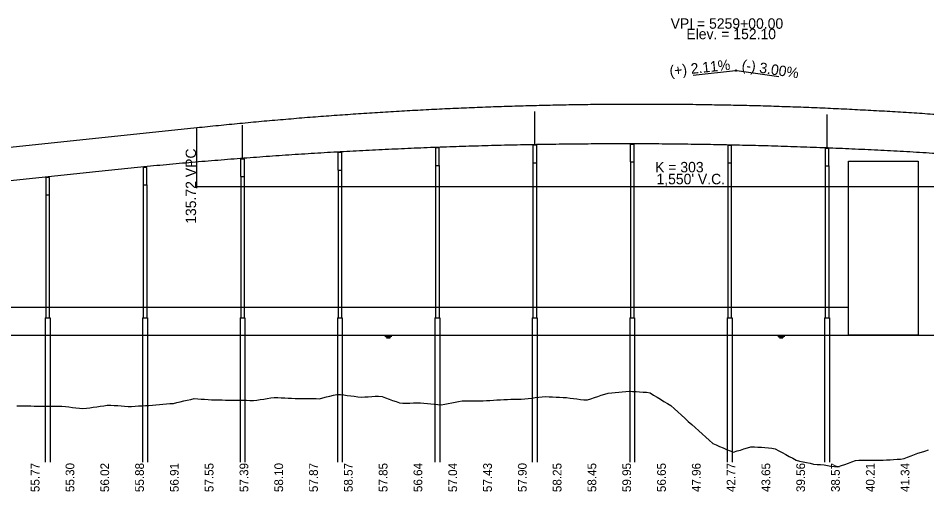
# Model space of a CAD drawing. Extents: x 2121671 to 2169879, y 557274 to 599957.
# Drawn here: x 2154437 to 2155742, y 595763 to 596443 of the extents above; entities that cross this region are included whole.
import ezdxf

# ---------------------------------------------------------------- set-up
doc = ezdxf.new("R2010")
doc.units = 0
for name, color, linetype in [('BR_CONCRETE', 7, 'Continuous'), ('BR_DETAILS', 7, 'Continuous'), ('BR_PRESTRESSED BEAM', 7, 'Continuous'), ('RD_DDB_GradeTX', 7, 'Continuous'), ('RD_DDB_Profile_Elev', 7, 'Continuous'), ('RD_DDB_Profile_EX', 7, 'Continuous'), ('RD_DDB_Profile_Lbl', 7, 'Continuous'), ('RD_DDB_Profile_PR', 7, 'Continuous'), ('RD_DDB_StripGrade', 7, 'Continuous'), ('RD_DDB_VCLbl', 7, 'Continuous')]:
    doc.layers.add(name, color=color, linetype=linetype)

msp = doc.modelspace()

# ---------------------------------------------------------------- linework, layer by layer
at = {"layer": 'BR_CONCRETE'}
for p, q in [((2155176.3, 596235.7), (2155176.3, 596013.1)), ((2155176.3, 596235.7), (2155176.3, 596013.1)), ((2155181.3, 596235.7), (2155181.3, 596013.1)), ((2155181.3, 596235.7), (2155181.3, 596013.1)), ((2155316.3, 596236.9), (2155316.3, 596013.1)), ((2155316.3, 596236.9), (2155316.3, 596013.1)), ((2155321.3, 596236.9), (2155321.3, 596013.1)), ((2155321.3, 596236.9), (2155321.3, 596013.1)), ((2155456.3, 596235.3), (2155456.3, 596013.1)), ((2155456.3, 596235.3), (2155456.3, 596013.1)), ((2155461.3, 596235.3), (2155461.3, 596013.1)), ((2155461.3, 596235.3), (2155461.3, 596013.1)), ((2154896.3, 596225.1), (2154896.3, 596013.1)), ((2154896.3, 596225.1), (2154896.3, 596013.1)), ((2154901.3, 596225.1), (2154901.3, 596013.1)), ((2154901.3, 596225.1), (2154901.3, 596013.1)), ((2155036.3, 596231.8), (2155036.3, 596013.1)), ((2155036.3, 596231.8), (2155036.3, 596013.1)), ((2155041.3, 596231.8), (2155041.3, 596013.1)), ((2155041.3, 596231.8), (2155041.3, 596013.1)), ((2155596.3, 596231), (2155596.3, 596013.1)), ((2155596.3, 596231), (2155596.3, 596013.1)), ((2155601.3, 596231), (2155601.3, 596013.1)), ((2155601.3, 596231), (2155601.3, 596013.1)), ((2154756.3, 596215.8), (2154756.3, 596013.1)), ((2154756.3, 596215.8), (2154756.3, 596013.1)), ((2154761.3, 596215.8), (2154761.3, 596013.1)), ((2154761.3, 596215.8), (2154761.3, 596013.1)), ((2154616.3, 596203.8), (2154616.3, 596013.1)), ((2154616.3, 596203.8), (2154616.3, 596013.1)), ((2154621.3, 596203.8), (2154621.3, 596013.1)), ((2154621.3, 596203.8), (2154621.3, 596013.1)), ((2154476.3, 596189.4), (2154476.3, 596013.1)), ((2154476.3, 596189.4), (2154476.3, 596013.1)), ((2154481.3, 596189.4), (2154481.3, 596013.1)), ((2154481.3, 596189.4), (2154481.3, 596013.1)), ((2154475.3, 596013.1), (2154475.3, 595805.8)), ((2154475.3, 596013.1), (2154475.3, 595805.8)), ((2154482.3, 596013.1), (2154482.3, 595805.8)), ((2154482.3, 596013.1), (2154482.3, 595805.8)), ((2154615.3, 596013.1), (2154615.3, 595805.8)), ((2154615.3, 596013.1), (2154615.3, 595805.8)), ((2154622.3, 596013.1), (2154622.3, 595805.8)), ((2154622.3, 596013.1), (2154622.3, 595805.8)), ((2154755.3, 596013.1), (2154755.3, 595805.8)), ((2154755.3, 596013.1), (2154755.3, 595805.8)), ((2154762.3, 596013.1), (2154762.3, 595805.8)), ((2154762.3, 596013.1), (2154762.3, 595805.8)), ((2154895.3, 596013.1), (2154895.3, 595805.8)), ((2154895.3, 596013.1), (2154895.3, 595805.8)), ((2154902.3, 596013.1), (2154902.3, 595805.8)), ((2154902.3, 596013.1), (2154902.3, 595805.8)), ((2155035.3, 596013.1), (2155035.3, 595805.8)), ((2155035.3, 596013.1), (2155035.3, 595805.8)), ((2155042.3, 596013.1), (2155042.3, 595805.8)), ((2155042.3, 596013.1), (2155042.3, 595805.8)), ((2155175.3, 596013.1), (2155175.3, 595805.8)), ((2155175.3, 596013.1), (2155175.3, 595805.8)), ((2155182.3, 596013.1), (2155182.3, 595805.8)), ((2155182.3, 596013.1), (2155182.3, 595805.8)), ((2155315.3, 596013.1), (2155315.3, 595805.8)), ((2155315.3, 596013.1), (2155315.3, 595805.8)), ((2155322.3, 596013.1), (2155322.3, 595805.8)), ((2155322.3, 596013.1), (2155322.3, 595805.8)), ((2155455.3, 596013.1), (2155455.3, 595805.8)), ((2155455.3, 596013.1), (2155455.3, 595805.8)), ((2155462.3, 596013.1), (2155462.3, 595805.8)), ((2155462.3, 596013.1), (2155462.3, 595805.8)), ((2155595.3, 596013.1), (2155595.3, 595805.8)), ((2155595.3, 596013.1), (2155595.3, 595805.8)), ((2155602.3, 596013.1), (2155602.3, 595805.8)), ((2155602.3, 596013.1), (2155602.3, 595805.8))]:
    msp.add_line(p, q, dxfattribs=at)
for points in [[(2155176.1, 596235.7), (2155181.6, 596235.7), (2155181.6, 596260.7), (2155176.1, 596260.7)], [(2155176.1, 596235.7), (2155181.6, 596235.7), (2155181.6, 596260.7), (2155176.1, 596260.7)], [(2155316.1, 596236.9), (2155321.6, 596236.9), (2155321.6, 596261.9), (2155316.1, 596261.9)], [(2155316.1, 596236.9), (2155321.6, 596236.9), (2155321.6, 596261.9), (2155316.1, 596261.9)], [(2154896.1, 596225.1), (2154901.6, 596225.1), (2154901.6, 596250.1), (2154896.1, 596250.1)], [(2154896.1, 596225.1), (2154901.6, 596225.1), (2154901.6, 596250.1), (2154896.1, 596250.1)], [(2155036.1, 596231.8), (2155041.6, 596231.8), (2155041.6, 596256.8), (2155036.1, 596256.8)], [(2155036.1, 596231.8), (2155041.6, 596231.8), (2155041.6, 596256.8), (2155036.1, 596256.8)], [(2155456.1, 596235.3), (2155461.6, 596235.3), (2155461.6, 596260.3), (2155456.1, 596260.3)], [(2155456.1, 596235.3), (2155461.6, 596235.3), (2155461.6, 596260.3), (2155456.1, 596260.3)], [(2155596.1, 596231), (2155601.6, 596231), (2155601.6, 596256), (2155596.1, 596256)], [(2155596.1, 596231), (2155601.6, 596231), (2155601.6, 596256), (2155596.1, 596256)], [(2154756.1, 596215.8), (2154761.6, 596215.8), (2154761.6, 596240.8), (2154756.1, 596240.8)], [(2154756.1, 596215.8), (2154761.6, 596215.8), (2154761.6, 596240.8), (2154756.1, 596240.8)], [(2154616.1, 596203.8), (2154621.6, 596203.8), (2154621.6, 596228.8), (2154616.1, 596228.8)], [(2154616.1, 596203.8), (2154621.6, 596203.8), (2154621.6, 596228.8), (2154616.1, 596228.8)], [(2154476.1, 596189.4), (2154481.6, 596189.4), (2154481.6, 596214.4), (2154476.1, 596214.4)], [(2154476.1, 596189.4), (2154481.6, 596189.4), (2154481.6, 596214.4), (2154476.1, 596214.4)]]:
    msp.add_lwpolyline(points, close=True, dxfattribs=at)
at = {"layer": 'BR_DETAILS'}
for points in [[(2155177.3, 596261.9), (2155178.3, 596261.9), (2155178.3, 596260.7), (2155177.3, 596260.7)], [(2155177.3, 596261.9), (2155178.3, 596261.9), (2155178.3, 596260.7), (2155177.3, 596260.7)], [(2155179.3, 596261.9), (2155180.3, 596261.9), (2155180.3, 596260.7), (2155179.3, 596260.7)], [(2155179.3, 596261.9), (2155180.3, 596261.9), (2155180.3, 596260.7), (2155179.3, 596260.7)], [(2155317.3, 596263.1), (2155318.3, 596263.1), (2155318.3, 596261.9), (2155317.3, 596261.9)], [(2155317.3, 596263.1), (2155318.3, 596263.1), (2155318.3, 596261.9), (2155317.3, 596261.9)], [(2155319.3, 596263.1), (2155320.3, 596263.1), (2155320.3, 596261.9), (2155319.3, 596261.9)], [(2155319.3, 596263.1), (2155320.3, 596263.1), (2155320.3, 596261.9), (2155319.3, 596261.9)], [(2155457.3, 596261.5), (2155458.3, 596261.5), (2155458.3, 596260.3), (2155457.3, 596260.3)], [(2155457.3, 596261.5), (2155458.3, 596261.5), (2155458.3, 596260.3), (2155457.3, 596260.3)], [(2155459.3, 596261.5), (2155460.3, 596261.5), (2155460.3, 596260.3), (2155459.3, 596260.3)], [(2155459.3, 596261.5), (2155460.3, 596261.5), (2155460.3, 596260.3), (2155459.3, 596260.3)], [(2154897.3, 596251.4), (2154898.3, 596251.4), (2154898.3, 596250.1), (2154897.3, 596250.1)], [(2154897.3, 596251.4), (2154898.3, 596251.4), (2154898.3, 596250.1), (2154897.3, 596250.1)], [(2154899.3, 596251.4), (2154900.3, 596251.4), (2154900.3, 596250.1), (2154899.3, 596250.1)], [(2154899.3, 596251.4), (2154900.3, 596251.4), (2154900.3, 596250.1), (2154899.3, 596250.1)], [(2155037.3, 596258), (2155038.3, 596258), (2155038.3, 596256.8), (2155037.3, 596256.8)], [(2155037.3, 596258), (2155038.3, 596258), (2155038.3, 596256.8), (2155037.3, 596256.8)], [(2155039.3, 596258), (2155040.3, 596258), (2155040.3, 596256.8), (2155039.3, 596256.8)], [(2155039.3, 596258), (2155040.3, 596258), (2155040.3, 596256.8), (2155039.3, 596256.8)], [(2155597.3, 596257.3), (2155598.3, 596257.3), (2155598.3, 596256), (2155597.3, 596256)], [(2155597.3, 596257.3), (2155598.3, 596257.3), (2155598.3, 596256), (2155597.3, 596256)], [(2155599.3, 596257.3), (2155600.3, 596257.3), (2155600.3, 596256), (2155599.3, 596256)], [(2155599.3, 596257.3), (2155600.3, 596257.3), (2155600.3, 596256), (2155599.3, 596256)], [(2154757.3, 596242.1), (2154758.3, 596242.1), (2154758.3, 596240.8), (2154757.3, 596240.8)], [(2154757.3, 596242.1), (2154758.3, 596242.1), (2154758.3, 596240.8), (2154757.3, 596240.8)], [(2154759.3, 596242.1), (2154760.3, 596242.1), (2154760.3, 596240.8), (2154759.3, 596240.8)], [(2154759.3, 596242.1), (2154760.3, 596242.1), (2154760.3, 596240.8), (2154759.3, 596240.8)], [(2154617.3, 596230), (2154618.3, 596230), (2154618.3, 596228.8), (2154617.3, 596228.8)], [(2154617.3, 596230), (2154618.3, 596230), (2154618.3, 596228.8), (2154617.3, 596228.8)], [(2154619.3, 596230), (2154620.3, 596230), (2154620.3, 596228.8), (2154619.3, 596228.8)], [(2154619.3, 596230), (2154620.3, 596230), (2154620.3, 596228.8), (2154619.3, 596228.8)], [(2154477.3, 596215.6), (2154478.3, 596215.6), (2154478.3, 596214.4), (2154477.3, 596214.4)], [(2154477.3, 596215.6), (2154478.3, 596215.6), (2154478.3, 596214.4), (2154477.3, 596214.4)], [(2154479.3, 596215.6), (2154480.3, 596215.6), (2154480.3, 596214.4), (2154479.3, 596214.4)], [(2154479.3, 596215.6), (2154480.3, 596215.6), (2154480.3, 596214.4), (2154479.3, 596214.4)]]:
    msp.add_lwpolyline(points, close=True, dxfattribs=at)
at = {"layer": 'BR_PRESTRESSED BEAM'}
for p, q in [((2155178.8, 596261.9), (2155178.8, 596309.4)), ((2155178.8, 596261.9), (2155178.8, 596309.4)), ((2155598.8, 596257.3), (2155598.8, 596304.8)), ((2155598.8, 596257.3), (2155598.8, 596304.8)), ((2154758.8, 596242.2), (2154758.8, 596289.7)), ((2154758.8, 596242.2), (2154758.8, 596289.7)), ((2154250.2, 596191.8), (2154543.2, 596222.7)), ((2154250.2, 596191.8), (2154543.2, 596222.7)), ((2154475.3, 596013.1), (2154482.3, 596013.1)), ((2154475.3, 596013.1), (2154482.3, 596013.1)), ((2154615.3, 596013.1), (2154622.3, 596013.1)), ((2154615.3, 596013.1), (2154622.3, 596013.1)), ((2154755.3, 596013.1), (2154762.3, 596013.1)), ((2154755.3, 596013.1), (2154762.3, 596013.1)), ((2154895.3, 596013.1), (2154902.3, 596013.1)), ((2154895.3, 596013.1), (2154902.3, 596013.1)), ((2155035.3, 596013.1), (2155042.3, 596013.1)), ((2155035.3, 596013.1), (2155042.3, 596013.1)), ((2155175.3, 596013.1), (2155182.3, 596013.1)), ((2155175.3, 596013.1), (2155182.3, 596013.1)), ((2155315.3, 596013.1), (2155322.3, 596013.1)), ((2155315.3, 596013.1), (2155322.3, 596013.1)), ((2155455.3, 596013.1), (2155462.3, 596013.1)), ((2155455.3, 596013.1), (2155462.3, 596013.1)), ((2155595.3, 596013.1), (2155602.3, 596013.1)), ((2155595.3, 596013.1), (2155602.3, 596013.1))]:
    msp.add_line(p, q, dxfattribs=at)
msp.add_spline([(2154543.2, 596222.7), (2154580.2, 596226.6), (2154617.2, 596230.2), (2154654.2, 596233.6), (2154691.2, 596236.9), (2154728.2, 596239.9), (2154765.2, 596242.8), (2154802.2, 596245.5), (2154839.2, 596248), (2154876.2, 596250.3), (2154913.2, 596252.4), (2154950.2, 596254.3), (2154987.2, 596256), (2155024.2, 596257.6), (2155061.2, 596258.9), (2155098.2, 596260.1), (2155135.2, 596261.1), (2155172.2, 596261.9), (2155209.2, 596262.5), (2155246.2, 596262.9), (2155283.2, 596263.1), (2155320.2, 596263.1), (2155357.2, 596263), (2155394.2, 596262.6), (2155431.2, 596262.1), (2155468.2, 596261.3), (2155505.2, 596260.4), (2155542.2, 596259.3), (2155579.2, 596258), (2155616.2, 596256.5), (2155653.2, 596254.9), (2155690.2, 596253), (2155727.2, 596251), (2155764.2, 596248.7), (2155801.2, 596246.3), (2155838.2, 596243.7), (2155875.2, 596240.9), (2155912.2, 596237.9), (2155949.2, 596234.7), (2155986.2, 596231.3), (2156023.2, 596227.7), (2156060.2, 596224), (2156097.2, 596220.1), (2156134.2, 596215.9), (2156171.2, 596211.6), (2156208.2, 596207.1), (2156245.2, 596202.4), (2156282.2, 596197.5), (2156319.2, 596192.4), (2156356.2, 596187.2), (2156393.2, 596181.7)], degree=3, dxfattribs=at)
msp.add_spline([(2154543.2, 596222.7), (2154580.2, 596226.6), (2154617.2, 596230.2), (2154654.2, 596233.6), (2154691.2, 596236.9), (2154728.2, 596239.9), (2154765.2, 596242.8), (2154802.2, 596245.5), (2154839.2, 596248), (2154876.2, 596250.3), (2154913.2, 596252.4), (2154950.2, 596254.3), (2154987.2, 596256), (2155024.2, 596257.6), (2155061.2, 596258.9), (2155098.2, 596260.1), (2155135.2, 596261.1), (2155172.2, 596261.9), (2155209.2, 596262.5), (2155246.2, 596262.9), (2155283.2, 596263.1), (2155320.2, 596263.1), (2155357.2, 596263), (2155394.2, 596262.6), (2155431.2, 596262.1), (2155468.2, 596261.3), (2155505.2, 596260.4), (2155542.2, 596259.3), (2155579.2, 596258), (2155616.2, 596256.5), (2155653.2, 596254.9), (2155690.2, 596253), (2155727.2, 596251), (2155764.2, 596248.7), (2155801.2, 596246.3), (2155838.2, 596243.7), (2155875.2, 596240.9), (2155912.2, 596237.9), (2155949.2, 596234.7), (2155986.2, 596231.3), (2156023.2, 596227.7), (2156060.2, 596224), (2156097.2, 596220.1), (2156134.2, 596215.9), (2156171.2, 596211.6), (2156208.2, 596207.1), (2156245.2, 596202.4), (2156282.2, 596197.5), (2156319.2, 596192.4), (2156356.2, 596187.2), (2156393.2, 596181.7)], degree=3, dxfattribs=at)
at = {"layer": 'RD_DDB_GradeTX'}
for p, q in [((2155406.6, 596361.4), (2155467.3, 596367.9)), ((2155529.6, 596358.8), (2155469.2, 596367.8))]:
    msp.add_line(p, q, dxfattribs=at)
msp.add_circle((2155468.2, 596368), 1, dxfattribs=at)
at = {"layer": 'RD_DDB_Profile_Elev'}
for p, q in [((2151940.7, 596028.1), (2155629.7, 596028.1)), ((2151972, 595988.1), (2156334.9, 595988.1)), ((2154963.4, 595986.8), (2154973.4, 595986.8)), ((2155528, 595986.8), (2155538, 595986.8)), ((2154964.7, 595985.6), (2154972.2, 595985.6)), ((2154965.9, 595984.3), (2154970.9, 595984.3)), ((2155529.3, 595985.6), (2155536.8, 595985.6)), ((2155530.5, 595984.3), (2155535.5, 595984.3))]:
    msp.add_line(p, q, dxfattribs=at)
msp.add_lwpolyline([(2155629.7, 596238.1), (2155729.7, 596238.1), (2155729.7, 595988.1), (2155629.7, 595988.1)], close=True, dxfattribs=at)
at = {"layer": 'RD_DDB_Profile_EX'}
for points in [[(2154434.5, 595886.7), (2154439.5, 595886.6), (2154444.5, 595886.6), (2154449.5, 595886.5), (2154454.5, 595886.4), (2154459.5, 595886.3), (2154464.5, 595886.3), (2154469.5, 595886.3), (2154474.5, 595886.3), (2154479.5, 595886.3), (2154484.5, 595886.3), (2154489.5, 595886.3), (2154494.5, 595886.3), (2154499.5, 595885.9), (2154504.5, 595885.4), (2154509.5, 595884.9), (2154514.5, 595884.3), (2154519.5, 595883.8), (2154524.5, 595883.3), (2154529.5, 595882.8), (2154534.5, 595883.1), (2154539.5, 595883.8), (2154544.5, 595884.5), (2154549.5, 595885.3), (2154554.5, 595886), (2154559.5, 595886.7), (2154564.5, 595887.4), (2154569.5, 595887.6), (2154574.5, 595887.2), (2154579.5, 595886.9), (2154584.5, 595886.5), (2154589.5, 595886.1), (2154594.5, 595885.7), (2154599.5, 595885.8), (2154604.5, 595886.1), (2154609.5, 595886.4), (2154614.5, 595886.7), (2154619.5, 595887), (2154624.5, 595887.2), (2154629.5, 595887.5), (2154634.5, 595887.9), (2154639.5, 595888.3), (2154644.5, 595888.8), (2154649.5, 595889.2), (2154654.5, 595889.7), (2154659.5, 595890.1), (2154664.5, 595891.2), (2154669.5, 595892.3), (2154674.5, 595893.5), (2154679.5, 595894.7), (2154684.5, 595895.8), (2154689.5, 595896.9), (2154694.5, 595896.6)], [(2154694.5, 595896.6), (2154699.5, 595896.3), (2154704.5, 595896), (2154709.5, 595895.7), (2154714.5, 595895.4), (2154719.5, 595895.2), (2154724.5, 595895.1), (2154729.5, 595895), (2154734.5, 595894.9), (2154739.5, 595894.8), (2154744.5, 595894.7), (2154749.5, 595894.8), (2154754.5, 595894.7), (2154759.5, 595894.6), (2154764.5, 595894.5), (2154769.5, 595894.4), (2154774.5, 595894.3), (2154779.5, 595894.7), (2154784.5, 595895.5), (2154789.5, 595896.3), (2154794.5, 595897.1), (2154799.5, 595897.9), (2154804.5, 595898.6), (2154809.5, 595898.4), (2154814.5, 595898.1), (2154819.5, 595897.9), (2154824.5, 595897.7), (2154829.5, 595897.4), (2154834.5, 595897.2), (2154839.5, 595897.2), (2154844.5, 595897.1), (2154849.5, 595897), (2154854.5, 595897), (2154859.5, 595896.9), (2154864.5, 595896.9), (2154869.5, 595896.8), (2154874.5, 595898), (2154879.5, 595899.3), (2154884.5, 595900.5), (2154889.5, 595901.7), (2154894.5, 595902.9), (2154899.5, 595902.9), (2154904.5, 595902.2), (2154909.5, 595901.5), (2154914.5, 595900.8), (2154919.5, 595900.2), (2154924.5, 595899.5), (2154929.5, 595899), (2154934.5, 595899.3), (2154939.5, 595899.6), (2154944.5, 595899.9), (2154949.5, 595900.2), (2154954.5, 595900.5), (2154959.5, 595900), (2154964.5, 595898.1), (2154969.5, 595896.3), (2154974.5, 595894.4), (2154979.5, 595892.6), (2154984.5, 595890.7), (2154989.5, 595890.4), (2154994.5, 595890.5), (2154999.5, 595890.6), (2155004.5, 595890.7), (2155009.5, 595890.8), (2155014.5, 595890.8), (2155019.5, 595890.6), (2155024.5, 595890.1), (2155029.5, 595889.6), (2155034.5, 595889), (2155039.5, 595888.5), (2155044.5, 595888.1), (2155049.5, 595889.1), (2155054.5, 595890), (2155059.5, 595891), (2155064.5, 595892), (2155069.5, 595892.9), (2155074.5, 595893.9), (2155079.5, 595893.9), (2155084.5, 595893.8), (2155089.5, 595893.8), (2155094.5, 595893.7), (2155099.5, 595893.7), (2155104.5, 595893.7), (2155109.5, 595894), (2155114.5, 595894.4), (2155119.5, 595894.7), (2155124.5, 595895.1), (2155129.5, 595895.4), (2155134.5, 595895.7), (2155139.5, 595895.8), (2155144.5, 595895.9), (2155149.5, 595896), (2155154.5, 595896.1), (2155159.5, 595896.2), (2155164.5, 595896.5), (2155169.5, 595897.1), (2155174.5, 595897.7), (2155179.5, 595898.3), (2155184.5, 595898.9), (2155189.5, 595899.5), (2155194.5, 595899.8)], [(2155194.5, 595899.8), (2155199.5, 595899.5), (2155204.5, 595899.3), (2155209.5, 595899.1), (2155214.5, 595898.9), (2155219.5, 595898.7), (2155224.5, 595898.4), (2155229.5, 595897.7), (2155234.5, 595897.1), (2155239.5, 595896.4), (2155244.5, 595895.7), (2155249.5, 595895), (2155254.5, 595895.1), (2155259.5, 595896.8), (2155264.5, 595898.5), (2155269.5, 595900.1), (2155274.5, 595901.8), (2155279.5, 595903.4), (2155284.5, 595904.7), (2155289.5, 595905.2), (2155294.5, 595905.7), (2155299.5, 595906.2), (2155304.5, 595906.7), (2155309.5, 595907.2), (2155314.5, 595907.4), (2155319.5, 595907.1), (2155324.5, 595906.9), (2155329.5, 595906.6), (2155334.5, 595906.4), (2155339.5, 595906.1), (2155344.5, 595905), (2155349.5, 595902), (2155354.5, 595899), (2155359.5, 595896), (2155364.5, 595893), (2155369.5, 595890), (2155374.5, 595887), (2155379.5, 595882.4), (2155384.5, 595877.8), (2155389.5, 595873.2), (2155394.5, 595868.6), (2155399.5, 595864), (2155404.5, 595859.6), (2155409.5, 595855.2), (2155414.5, 595850.7), (2155419.5, 595846.2), (2155424.5, 595841.7), (2155429.5, 595837.2), (2155434.5, 595832.6), (2155439.5, 595830.5), (2155444.5, 595828.3), (2155449.5, 595826.2), (2155454.5, 595824), (2155459.5, 595821.8), (2155464.5, 595820.2), (2155469.5, 595821.7), (2155474.5, 595823.1), (2155479.5, 595824.6), (2155484.5, 595826), (2155489.5, 595827.5), (2155494.5, 595827.9), (2155499.5, 595827.4), (2155504.5, 595827), (2155509.5, 595826.5), (2155514.5, 595826.1), (2155519.5, 595825.6), (2155524.5, 595824.8), (2155529.5, 595822.1), (2155534.5, 595819.4), (2155539.5, 595816.7), (2155544.5, 595813.9), (2155549.5, 595811.2), (2155554.5, 595808.4), (2155559.5, 595807.1), (2155564.5, 595806), (2155569.5, 595805), (2155574.5, 595804), (2155579.5, 595803), (2155584.5, 595802.5), (2155589.5, 595802.3), (2155594.5, 595801.6), (2155599.5, 595800.8), (2155604.5, 595800.1), (2155609.5, 595799.3), (2155614.5, 595799), (2155619.5, 595800.8), (2155624.5, 595802.5), (2155629.5, 595804.3), (2155634.5, 595806.1), (2155639.5, 595807.9), (2155644.5, 595808.5), (2155649.5, 595808.5), (2155654.5, 595808.5), (2155659.5, 595808.5), (2155664.5, 595808.5), (2155669.5, 595808.5), (2155674.5, 595808.3), (2155679.5, 595808.5), (2155684.5, 595808.9), (2155689.5, 595809.2), (2155694.5, 595809.6)], [(2155694.5, 595809.6), (2155699.5, 595810), (2155704.5, 595809.8), (2155709.5, 595810.9), (2155714.5, 595812.7), (2155719.5, 595814.6), (2155724.5, 595816.5), (2155729.5, 595818.4), (2155734.5, 595819.9), (2155739.5, 595821.3), (2155744.5, 595823.3)]]:
    msp.add_lwpolyline(points, dxfattribs=at)
at = {"layer": 'RD_DDB_Profile_PR'}
msp.add_line((2154250.2, 596239.3), (2154693.2, 596286.1), dxfattribs=at)
msp.add_spline([(2154693.2, 596286.1), (2154724.2, 596289.3), (2154755.2, 596292.3), (2154786.2, 596295.2), (2154817.2, 596297.9), (2154848.2, 596300.5), (2154879.2, 596302.9), (2154910.2, 596305.1), (2154941.2, 596307.2), (2154972.2, 596309.1), (2155003.2, 596310.9), (2155034.2, 596312.5), (2155065.2, 596314), (2155096.2, 596315.3), (2155127.2, 596316.4), (2155158.2, 596317.4), (2155189.2, 596318.2), (2155220.2, 596318.9), (2155251.2, 596319.4), (2155282.2, 596319.7), (2155313.2, 596319.9), (2155344.2, 596319.9), (2155375.2, 596319.8), (2155406.2, 596319.5), (2155437.2, 596319), (2155468.2, 596318.4), (2155499.2, 596317.7), (2155530.2, 596316.7), (2155561.2, 596315.7), (2155592.2, 596314.4), (2155623.2, 596313), (2155654.2, 596311.4), (2155685.2, 596309.7), (2155716.2, 596307.9), (2155747.2, 596305.8), (2155778.2, 596303.6), (2155809.2, 596301.3), (2155840.2, 596298.8), (2155871.2, 596296.1), (2155902.2, 596293.3), (2155933.2, 596290.3), (2155964.2, 596287.1), (2155995.2, 596283.8), (2156026.2, 596280.4), (2156057.2, 596276.8), (2156088.2, 596273), (2156119.2, 596269), (2156150.2, 596264.9), (2156181.2, 596260.7), (2156212.2, 596256.3), (2156243.2, 596251.7)], degree=3, dxfattribs=at)
at = {"layer": 'RD_DDB_VCLbl'}
for p, q in [((2154693.2, 596199.2), (2154693.2, 596286.1)), ((2154693.2, 596201.7), (2156243.2, 596201.7))]:
    msp.add_line(p, q, dxfattribs=at)

# ---------------------------------------------------------------- texts
at = {"layer": 'RD_DDB_GradeTX'}
for s, rotation, p in [('(+) 2.11%', 6.0299, (2155373.3, 596359.9)), ('(-) 3.00%', 351.4692, (2155475.5, 596368.9))]:
    msp.add_text(s, height=15, rotation=rotation, dxfattribs=at).set_placement(p)
at = {"layer": 'RD_DDB_Profile_Lbl'}
for s, p in [('VPI = 5259+00.00', (2155374.1, 596428)), ('Elev. = 152.10', (2155396.7, 596413))]:
    msp.add_text(s, height=15, dxfattribs=at).set_placement(p)
at = {"layer": 'RD_DDB_StripGrade'}
for s, height, p in [('135.72 VPC', 15, (2154692.2, 596147.9)), ('55.77', 12.5, (2154467.2, 595762.7)), ('55.30', 12.5, (2154517.2, 595762.7)), ('56.02', 12.5, (2154567.2, 595762.7)), ('55.88', 12.5, (2154617.2, 595762.7)), ('56.91', 12.5, (2154667.2, 595762.7)), ('57.55', 12.5, (2154717.2, 595762.7)), ('57.39', 12.5, (2154767.2, 595762.7)), ('58.10', 12.5, (2154817.2, 595762.7)), ('57.87', 12.5, (2154867.2, 595762.7)), ('58.57', 12.5, (2154917.2, 595762.7)), ('57.85', 12.5, (2154967.2, 595762.7)), ('56.64', 12.5, (2155017.2, 595762.7)), ('57.04', 12.5, (2155067.2, 595762.7)), ('57.43', 12.5, (2155117.2, 595762.7)), ('57.90', 12.5, (2155167.2, 595762.7)), ('58.25', 12.5, (2155217.2, 595762.7)), ('58.45', 12.5, (2155267.2, 595762.7)), ('59.95', 12.5, (2155317.2, 595762.7)), ('56.65', 12.5, (2155367.2, 595762.7)), ('47.96', 12.5, (2155417.2, 595762.7)), ('42.77', 12.5, (2155467.2, 595762.7)), ('43.65', 12.5, (2155517.2, 595762.7)), ('39.56', 12.5, (2155567.2, 595762.7)), ('38.57', 12.5, (2155617.2, 595762.7)), ('40.21', 12.5, (2155667.2, 595762.7)), ('41.34', 12.5, (2155717.2, 595762.7))]:
    msp.add_text(s, height=height, rotation=90, dxfattribs=at).set_placement(p)
at = {"layer": 'RD_DDB_VCLbl'}
for s, p in [('K = 303', (2155351.8, 596221.8)), ("1,550' V.C.", (2155353.7, 596204.7))]:
    msp.add_text(s, height=15, dxfattribs=at).set_placement(p)

doc.saveas('drawing.dxf')
